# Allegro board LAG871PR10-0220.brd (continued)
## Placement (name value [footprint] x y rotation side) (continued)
PR504  0_0402_5%  [R0402_0OHM]  178.82 104.25 90 top
PR505  1M_0402_1%  [R_0402]  177.11 105.16 90 top
PR506  10K_0402_1%  [R_0402]  181.76 103.16 270 bottom
PR513  0_0402_5%  [R0402_0OHM]  127.97 25.58 180 top
PR514  1M_0402_1%  [R_0402]  126.27 25.23 270 top
PR515  21.5K_0402_1%  [R_0402]  118.05 26.87 270 top
PR516  10K_0402_1%  [R_0402]  118.94 25.1 270 top
PR601  45.3_0402_1%  [R_0402]  56.88 59.04 0 top
PR602  0_0402_5%  [R0402_0OHM]  59.97 61.64 90 top
PR603  0_0402_5%  [R0402_0OHM]  58.45 64.12 180 top
PR604  75_0402_1%  [R_0402]  56.88 59.9 0 top
PR605  100_0402_1%  [R_0402]  56.88 60.75 0 top
PR606  0_0402_5%  [R0402_0OHM]  90.57 96.79 270 top
PR608  100K_0402_5%  [R_0402]  60.1 64.12 180 top
PR610  10K_0402_1%  [R_0402]  62.46 53.79 90 top
PR611  9.31K_0402_1%  [R_0402]  60.1 65 180 top
PR612  1.91K_0402_1%  [R_0402]  59.02 58.21 0 top
PR613  97.6K_0402_1%  [R_0402]  60.73 53.75 90 top
PR614  0_0402_5%  [R0402_0OHM]  59.02 57.32 0 top
PR615  0_0402_5%  [R_0402]  72.4 54.4 90 top
PR616  0_0402_5%  [R0402_0OHM]  58.94 55.61 0 top
PR617  4.3K_0402_1%  [R_0402]  63.28 53.77 90 top
PR618  49.9_0402_1%  [R_0402]  59.02 59.04 0 top
PR619  2.2_0603_5%  [R_0603]  95.14 97.61 270 bottom
PR620  0_0402_5%  [R0402_0OHM]  58.94 54.72 0 top
PR621  316_0402_1%  [R_0402]  66.03 51.78 90 top
PR622  2.49K_0402_1%  [R_0402]  67.72 52.69 180 top
PR623  2K_0402_1%  [R_0402]  65.14 53.57 0 top
PR624  3.65K_0603_1%  [R_0603]  91.69 90.61 180 top
PR625  0_0402_5%  [R0402_0OHM]  59.04 59.9 0 top
PR626  10_0402_1%  [R_0402]  59.02 60.75 0 top
PR627  4.7_1206_5%  [R_1206]  94.11 91.99 270 top
PR628  4.99K_0402_1%  [R_0402]  82.99 86.06 180 top
PR629  86.6K_0402_1%  [R_0402]  74.19 54.41 180 top
PR630  2.49K_0402_1%  [R_0402]  70.34 65.63 90 top
PR631  27.4K_0402_1%  [R_0402]  61.62 52.85 0 top
PR632  1K_0402_1%  [R_0402]  71.98 51.63 0 top
PR633  11K_0402_1%  [R_0402]  69.66 52.61 0 top
PR634  0_0402_5%  [R_0402]  73.27 52.7 0 top
PR635  10K_0402_1%  [R_0402]  74.22 56.17 180 top
PR636  634_0402_1%  [R_0402]  62.93 65.45 90 top
PR638  523_0402_1%  [R_0402]  71.43 52.65 90 top
PR639  3.09K_0402_1%  [R_0402]  74.21 57.88 180 top
PR640  365_0402_1%  [R_0402]  74.23 65.46 0 top
PR641  1K_0402_1%  [R_0402]  62.14 67.77 90 top
PR642  2.61K_0402_1%  [R_0402]  90.63 89.47 270 top
PR643  11K_0402_1%  [R_0402]  65.22 70.56 270 top
PR644  1K_0402_1%  [R_0402]  74.35 67.2 270 top
PR645  316_0402_1%  [R_0402]  74.16 60.76 180 top
PR646  316_0402_1%  [R_0402]  67.51 65.65 90 top
PR647  27.4K_0402_1%  [R_0402]  75.04 55.26 90 top
PR648  1.91K_0402_1%  [R_0402]  74.15 59.05 180 top
PR649  1.62K_0402_1%  [R_0402]  66.55 65.74 90 top
PR650  2K_0402_1%  [R_0402]  73.23 59.9 0 top
PR651  39.2K_0402_1%  [R_0402]  71.53 66.52 0 top
PR652  2K_0402_1%  [R_0402]  68.41 65.63 90 top
PR653  20M_0402_5%  [R_0402]  76.61 62.44 90 top
PR656  11K_0402_1%  [R_0402]  74.21 63.66 90 top
PR657  4.42K_0402_1%  [R_0402]  87.43 66.8 0 top
PR658  20M_0402_5%  [R_0402]  69.29 51.68 270 top
PR659  0_0402_5%  [R0402_0OHM]  79.95 86.49 180 bottom
PR660  3.9_0603_1%  [R_0603]  76.26 85.01 90 bottom
PR661  3.65K_0603_1%  [R_0603]  82.21 69.55 270 top
PR662  0_0402_5%  [R0402_0OHM]  71.84 66.13 90 bottom
PR663  4.7_1206_5%  [R_1206]  82.72 93.5 180 top
PR664  0_0402_5%  [R0402_0OHM]  72.64 66.13 90 bottom
PR665  3.9_0603_1%  [R_0603]  71.12 70.37 0 bottom
PR666  10_0402_1%  [R_0402]  83.93 88 180 top
PR667  3.65K_0603_1%  [R_0603]  87.33 91.04 90 top
PR668  100K_0402_1%  [R_0402]  88.33 92.56 270 top
PR669  4.7_1206_5%  [R_1206]  81.03 71.11 0 top
PR670  100K_0402_1%  [R_0402]  88.42 77.27 270 top
PR671  0_0402_5%  [R0402_0OHM]  76.02 76.02 90 bottom
PR672  3.9_0603_1%  [R_0603]  74.62 79.67 0 bottom
PR673  10_0402_1%  [R_0402]  89.24 77.27 270 top
PR674  3.65K_0603_1%  [R_0603]  85.79 76.14 90 top
PR675  100K_0402_1%  [R_0402]  84.77 76.46 270 top
PR676  4.7_1206_5%  [R_1206]  83.59 77.68 90 top
PR677  100K_0402_1%  [R_0402]  83.88 74.8 0 top
PR678  100_0402_1%  [R_0402]  58.94 56.37 0 top
PR679  0_0402_5%  [R0402_0OHM]  92.47 92.83 270 top
PR680  1_0603_5%  [R_0603]  71.24 69.29 270 bottom
PR687  0_0402_5%  [R0402_0OHM]  80.99 86.56 90 bottom
PR688  1_0603_5%  [R_0603]  79.53 87.04 180 top
PR691  1_0603_5%  [R_0603]  74.89 77.13 90 bottom
PR692  0_0402_5%  [R0402_0OHM]  76.32 75.24 0 bottom
PR693  11.8K_0402_1%  [R_0402]  59.84 53.03 90 top
PR700  0.01_1206_1%  [R_1206_4P-D]  51.75 83.74 0 bottom
PR701  1_0603_1%  [R_0603]  44.11 59.48 270 bottom
PR702  1_0603_1%  [R_0603]  47.06 61.2 270 bottom
PR703  0_0603_5%  [R_0603]  40.33 56.37 0 top
PR704  3.3_0603_1%  [R_0603]  44.35 57.52 0 top
PR705  442K_0402_1%  [R_0402]  39.02 55.31 0 top
PR706  100K_0402_5%  [R_0402]  39.94 54.43 180 top
PR707  4.7_0603_5%  [R_0603]  52.08 56.67 0 top
PR708  1_0805_5%~D  [R_0805]  43.69 60.04 90 top
PR709  0_0402_5%  [R0402_0OHM]  38.66 53.46 0 top
PR710  100K_0402_1%  [R_0402]  54.48 58.63 180 top
PR711  0.005_1206_1%  [R_1206_4P-D]  225.7 40.61 0 bottom
PR712  0_0402_5%  [R_0402]  53.56 57.8 0 top
PR713  0_0402_5%  [R0402_0OHM]  40.9 53.34 0 top
PR714  4.7_0603_5%  [R_0603]  52.86 55.44 180 top
PR715  0_0402_5%  [R0402_0OHM]  40.9 52.55 0 top
PR716  154K_0402_1%  [R_0402]  55.22 58.65 270 top
PR717  4.7_1206_5%  [R_1206]  59.89 72.45 180 top
PR718  4.7_1206_5%  [R_1206]  60.44 74.44 180 top
PR719  0_0402_5%  [R0402_0OHM]  40.9 51.77 0 top
PR720  1M_0402_1%  [R_0402]  42.51 69.75 180 top
PR721  0_0402_5%  [R0402_0OHM]  51.37 53.19 0 top
PR722  0_0402_5%  [R0402_0OHM]  40.95 50.79 0 top
PR723  100K_0402_1%  [R_0402]  41.24 49.21 270 top
PR724  100K_0402_1%  [R_0402]  41.2 50.03 0 top
PR725  105K_0402_1%  [R_0402]  44.7 49.26 270 top
PR726  100K_0402_1%  [R_0402]  43.88 48.3 90 top
PR727  0_0402_5%  [R0402_0OHM]  40.21 48.26 90 top
PR728  499_0402_1%  [R_0402]  45.5 49.27 270 top
PR729  0_0402_5%  [R0402_0OHM]  48.86 49.27 270 top
PR731  0_0402_5%  [R0402_0OHM]  49.69 49.27 270 top
PR733  1_0603_1%  [R_0603]  53.3 50.26 0 top
PR734  1_0603_1%  [R_0603]  53.37 48.16 270 top
PR735  0_0402_5%  [R_0402]  46.53 64.83 180 top
PR736  0_0402_5%  [R0402_0OHM]  47.29 63.95 90 top
PR737  0_0402_5%  [R0402_0OHM]  48.08 63.95 90 top
PR738  100_0402_5%  [R_0402]  51.06 46.87 270 top
PR739  100K_0402_1%  [R_0402]  45.71 68.93 0 top
PR740  0_0402_5%  [R0402_0OHM]  43.75 64.8 180 top
PR741  0_0402_5%  [R0402_0OHM]  44.95 70.12 270 top
PR743  0_0402_5%  [R0402_0OHM]  47.21 49.27 270 top
PR744  100K_0402_1%  [R_0402]  42.08 64.78 90 top
PR745  0_0402_5%  [R_0402]  43.08 48.3 90 top
PR746  0_0402_5%  [R_0402]  36.95 53.02 0 top
PR800  422K_0402_1%  [R_0402]  49.57 75.95 180 top
PR801  300K_0402_5%  [R_0402]  43.42 89.91 180 top
PR802  300K_0402_5%  [R_0402]  50.17 77.38 270 bottom
PR803  499K_0402_1%  [R_0402]  44.02 85.03 0 bottom
PR804  499K_0402_1%  [R_0402]  48.39 77.41 270 bottom
PR805  1.8M_0402_1%  [R_0402]  48.67 76.73 0 top
PR806  1K_0402_1%  [R_0402]  42.23 73.64 90 top
PR807  100K_0402_5%  [R_0402]  42.51 90.7 0 top
PR808  100K_0402_5%  [R_0402]  47.34 93.16 0 top
PR809  102K_0402_1%  [R_0402]  43.12 73.64 90 top
PR810  100K_0402_5%  [R_0402]  45.36 103.86 270 top
PR811  49.9K_0402_1%  [R_0402]  38.15 93.01 90 top
PR812  49.9K_0402_1%  [R_0402]  34.31 95.08 90 top
PR813  100K_0402_5%  [R_0402]  44.58 103.88 180 top
PR814  0_0402_5%  [R0402_0OHM]  47.43 99.07 180 top
PR815  37.4K_0402_1%  [R_0402]  44.89 73.65 0 top
PR816  0_0402_5%  [R0402_0OHM]  37.33 93.02 90 top
PR817  24.9K_0402_1%  [R_0402]  46.86 74.61 0 top
PR818  0_0402_5%  [R0402_0OHM]  36.9 98.36 180 top
PR819  100K_0402_5%  [R_0402]  36.53 93.01 90 top
PR820  0_0402_5%  [R0402_0OHM]  44.84 94.9 180 top
PR821  100K_0402_5%  [R_0402]  42.86 101.64 270 top
PR822  100K_0402_5%  [R_0402]  40.45 103.1 0 top
PR823  100K_0402_5%  [R_0402]  42.53 87.29 90 top
PR824  100K_0402_5%  [R_0402]  36.96 105.99 270 top
PR825  100K_0402_5%  [R_0402]  34.3 105.99 270 top
PR826  0_0402_5%  [R0402_0OHM]  33.47 105.99 270 top
PR827  0_0402_5%  [R0402_0OHM]  35.29 100.26 90 top
PR828  100K_0402_5%  [R_0402]  38.61 105.07 90 top
PR829  0_0402_5%  [R0402_0OHM]  52.1 105.95 0 top
PR830  100K_0402_5%  [R_0402]  37.79 105.07 90 top
PR831  499K_0402_1%  [R_0402]  46.81 84.63 270 top
PR832  102K_0402_1%  [R_0402]  42.41 80.38 0 top
PR833  100K_0402_5%  [R_0402]  42.18 106.04 180 top
PR834  0_0402_5%  [R0402_0OHM]  36.86 100.17 90 top
PR835  47K_0402_1%  [R_0402]  41.66 84.78 270 top
PR836  0_0402_5%  [R0402_0OHM]  43.36 86.04 180 top
PR838  100K_0402_5%  [R_0402]  36.14 105.99 270 top
PR839  100K_0402_5%  [R_0402]  42.18 106.86 180 top
PR840  0_0402_5%  [R0402_0OHM]  42.45 83.86 90 top
PR841  0_0402_5%  [R_0402]  37.86 100.16 90 top
PR842  97.6K_0402_1%  [R_0402]  48.55 80.26 0 top
PR843  37.4K_0402_1%  [R_0402]  43.33 78.61 180 top
PR844  0_0402_5%  [R0402_0OHM]  41.27 105.21 0 top
PR845  0_0402_5%  [R_0402]  41.27 104.39 0 top
PR846  10K_0402_5%  [R_0402]  42.68 95.19 270 top
PR851  100K_0402_5%  [R_0402]  43.65 103.05 0 top
PR852  100K_0402_5%  [R_0402]  42.85 102.43 90 top
PR853  0_0402_5%  [R0402_0OHM]  44.23 94.13 0 top
PR854  0_0402_5%  [R0402_0OHM]  47.57 92.41 270 top
PR855  10K_0402_5%  [R_0402]  43.45 93.61 270 top
PR856  0_0402_5%  [R_0402]  43.54 96.63 270 top
PR857  0_0402_5%  [R0402_0OHM]  44.32 95.71 90 top
PR858  0_0402_5%  [R0402_0OHM]  41.64 95.66 90 top
PR859  0_0402_5%  [R0402_0OHM]  47.07 90.67 180 top
PR860  0_0402_5%  [R_0402]  45.79 88.88 90 top
PR861  0_0402_5%  [R0402_0OHM]  38.23 97.33 90 top
PR862  100K_0402_5%  [R_0402]  45.84 75.18 0 bottom
PR865  100K_0402_5%  [R_0402]  50.87 96.54 180 top
PR866  0_0402_5%  [R0402_0OHM]  42.41 81.16 0 top
PR870  499K_0402_1%  [R_0402]  49.46 79.47 180 top
PR892  22_0805_5%  [R_0805]  60.98 91.24 270 bottom
PR893  22_0805_5%  [R_0805]  59.02 94.28 180 bottom
PR953  100_0402_5%  [R_0402]  41.28 40.81 90 bottom
PR954  100_0402_5%  [R_0402]  40.52 40.81 90 bottom
PR955  100_0402_5%  [R_0402]  37.6 40.24 90 bottom
PR956  0_0402_5%  [R_0402]  36.77 40.24 90 bottom
PR3001  0_0402_5%  [R_0402]  48.53 51.86 180 bottom
PR3002  200K_0402_1%  [R_0402]  53.04 61.93 270 bottom
PR3003  300K_0402_1%  [R_0402]  53.82 61.92 270 bottom
PR3004  200K_0402_1%  [R_0402]  47.81 58.81 0 bottom
PR3005  100K_0402_1%  [R_0402]  49.98 57.4 180 bottom
PR3006  0_0402_5%  [R_0402]  45.55 66.22 180 bottom
PR3007  237K_0402_1%  [R_0402]  44.63 65.46 0 bottom
PR3008  43.2K_0402_1%  [R_0402]  46.41 64.19 0 bottom
PR3009  14.7K_0402_1%  [R_0402]  48.95 60.43 180 bottom
PR3010  147K_0402_1%  [R_0402]  48.95 61.22 180 bottom
PR3011  43.2K_0402_1%  [R_0402]  47.33 62.41 180 bottom
PR3012  1K_0201_1%  [R_0201]  52.34 61.47 270 bottom
PR3013  1K_0201_1%  [R_0201]  51.66 63.28 180 bottom
PU2  RT9058-33GX_SOT89-3  [AP2204R-5P0TRG1_SOT89-3]  63.34 93.36 0 bottom
PU3  MC74VHC1G08DFT2G_SC70-5  [TC7SH08FU_SSOP5]  51.63 93.91 270 top
PU100  -  [SY8288BRAC_QFN20_3X3]  191.58 98.97 270 top
PU102  SYV828CRAC_QFN20_3X3  [SY8288CRAC_QFN20_3X3]  43.54 26.66 90 top
PU200  -  [SY8210AQVC_QFN19_4X3]  223.44 27.3 180 top
PU301  SY8286RAC_QFN20_3X3  [SY8288RAC_QFN20_3X3]  190.78 108.94 0 top
PU401  SY8057BQDC_QFN16_3X3  [SY8057QDC_QFN16_3X3]  83.31 28.18 0 top
PU402  SY8057CQDC_QFN16_3X3  [SY8057QDC_QFN16_3X3]  185.21 26.78 180 top
PU501  -  [RT8097ALGE_SOT23-6]  178.8 104.62 90 bottom
PU503  EM1109V-AD_DFN3308-8_3X3  [AP7361C-FGE-7_U-DFN3030-8_3X3]  120.85 26.55 270 top
PU602  ISL95857CHRTZ-T_TQFN40_5X5  [ISL62883CHRTZ-T_TQFN40_5X5-S]  64.52 56.53 0 top
PU610  FDMF3035_PQFN31_5X5  [NCP302045MNTWG_PQFN33_5X5]  79.14 87.66 180 bottom
PU612  FDMF3035_PQFN31_5X5  [NCP302045MNTWG_PQFN33_5X5]  73.82 68.11 90 bottom
PU613  FDMF3035_PQFN31_5X5  [NCP302045MNTWG_PQFN33_5X5]  77.29 77.37 90 bottom
PU614  ISL95808HRZ-TS2778_DFN8_2X2~D  [ISL95808HRZ-TS2378_DFN8_2X2-S]  92.97 96.34 180 top
PU700  ISL9538BHRTZ-T_TQFN32_4X4  [ISL88738HRTZ-T_TQFN32_4X4]  48.98 52.45 180 top
PU701  MC74VHC1G08DFT2G_SC70-5  [TC7SH08FU_SSOP5]  44.89 67.81 180 top
PU800  AS393MMTR-G1_MSOP8  [LM393DGKR_VSSOP8]  45.2 76.24 90 top
PU801  MC74VHC1G08DFT2G_SC70-5  [TC7SH08FU_SSOP5]  46.4 91.87 90 top
PU3000  -  [AZV3002RL-7_U-FLGA8_1P65X1P65]  51.28 61.11 180 bottom
QC2  PJX138K_SOT563-6  [DMN63D8LV-7_SOT563-6]  172.85 77.46 270 bottom
QC4  PJX138K_SOT563-6  [DMN63D8LV-7_SOT563-6]  169.46 96.9 180 bottom
QC6  -  [L2N7002WT1G_SC-70-3]  174.97 60.24 180 top
QC7  NTK3139PT1G_SOT723-3  [PW567EA_SOT-723-3]  172.03 62.05 180 top
QE2  PJX138K_SOT563-6  [DMN63D8LV-7_SOT563-6]  279.6 64.96 0 top
QE3  -  [LMBT3904WT1G_SC70-3]  121.33 75.33 0 top
QE4  -  [LMBT3904WT1G_SC70-3]  176.41 97.78 270 bottom
QE5  -  [LMBT3904WT1G_SC70-3]  17.16 27.37 270 bottom
QE6  -  [LMBT3904WT1G_SC70-3]  89.29 96.44 180 bottom
QE7  -  [LMBT3904WT1G_SC70-3]  208.16 37.65 180 bottom
QE11  -  [L2N7002WT1G_SC-70-3]  171.4 100.45 270 bottom
QE12  -  [L2N7002WT1G_SC-70-3]  263.52 86.35 180 top
QE15  LP2301BLT1G_SOT23-3  [LP2301ALT1G_SOT23-3]  270.26 68.79 180 top
QE17  -  [L2N7002WT1G_SC-70-3]  274.91 66.56 90 top
QR1  -  [L2N7002WT1G_SC-70-3]  286.58 50.16 180 top
QV1  -  [AO6405_TSOP6]  91.47 99.2 0 bottom
QV2  -  [2N7002KTB_SOT523-3]  99.71 101.78 180 bottom
QV3  L2N7002DW1T1G_SC88-6  [DMN65D8LDW-7_SOT363-6]  9.33 54.98 0 bottom
QV4  -  [2N7002KTB_SOT523-3]  15.69 61.33 90 top
QV5  -  [2N7002KTB_SOT523-3]  16.17 67.43 0 top
QV7  -  [2N7002KTB_SOT523-3]  80.7 106.79 90 top
QV8  NTK3139PT1G_SOT723-3  [PW567EA_SOT-723-3]  78.21 108.72 0 top
QV18  -  [MMBT3906H_SOT23-3]  75.02 104.15 180 top
QV19  -  [LMBT3904WT1G_SC70-3]  88.14 100.45 90 top
QV20  -  [MMBT3906H_SOT23-3]  93.41 106 180 top
QV21  -  [LMBT3904WT1G_SC70-3]  89.48 100.45 270 top
QZ1  NTK3139PT1G_SOT723-3  [PW567EA_SOT-723-3]  52.25 107.98 0 top
QZ3  -  [LMUN5111T1G_SC70-3]  306.09 9.14 0 bottom
QZ7  L2N7002DW1T1G_SC88-6  [DMN65D8LDW-7_SOT363-6]  308.52 69.64 180 bottom
QZ15  -  [PJE138K_SOT523-3]  248.56 37.58 0 bottom
QZ17  -  [PJE138K_SOT523-3]  269.02 54.37 0 top
QZ18  NTK3139PT1G_SOT723-3  [PW567EA_SOT-723-3]  308.18 94.23 270 bottom
QZ21  -  [LMBT3904WT1G_SC70-3]  298.99 12.44 180 top
QZ22  -  [PJE138K_SOT523-3]  30.79 32.25 0 top
RA3  0_0603_5%  [R0603_0OHM]  282.96 34.79 270 top
RA5  2.2K_0402_5%  [R_0402]  288.01 39.73 180 top
RA6  2.2K_0402_5%  [R_0402]  288.01 40.62 180 top
RA7  16.2_0402_1%  [R_0402]  287.85 37.83 90 top
RA8  16.2_0402_1%  [R_0402]  288.93 36.71 270 top
RA9  33_0402_5%  [R_0402]  274.57 35.36 0 top
RA12  1K_0402_5%  [R_0402]  282.96 56.31 90 top
RA13  1K_0402_5%  [R_0402]  287.71 56.95 0 top
RA14  22_0402_5%  [R_0402]  276.75 39.68 180 top
RA17  33_0402_5%  [R_0402]  276.73 37.26 180 top
RA18  10K_0402_5%  [R_0402]  273.96 44.57 180 top
RA35  0_0402_5%  [R0402_0OHM]  295.86 43.8 135 top
RA36  0_0402_5%  [R0402_0OHM]  283.34 49.57 90 top
RA37  0_0402_5%  [R0402_0OHM]  295.92 33.28 270 top
RA44  100K_0402_5%  [R_0402]  286.71 47.8 90 top
RA45  10K_0402_5%  [R_0402]  286.14 58.08 90 top
RA48  0_0201_5%  [R0201_0OHM]  273.37 46.64 270 top
RA50  0_0201_5%  [R_0201]  272.36 44.41 90 top
RA51  10K_0402_5%  [R_0402]  284.74 56.31 90 top
RA52  100K_0402_5%  [R_0402]  275.84 41.14 0 top
RA53  0_0402_5%  [R0402_0OHM]  286.33 42.08 0 top
RA54  0_0402_5%  [R_0402]  285.76 42.84 0 top
RA59  100K_0402_1%  [R_0402]  275.98 46.4 270 top
RA60  200K_0402_1%  [R_0402]  275.23 45.97 180 top
RA61  100K_0402_1%  [R_0402]  277.57 44.88 135 top
RA66  10K_0402_5%  [R_0402]  304.88 17.56 270 bottom
RA67  10K_0402_5%  [R_0402]  305.7 17.56 270 bottom
RC2  100K_0402_5%  [R_0402]  168.08 88.51 0 bottom
RC5  121_0402_1%  [R_0402]  140.12 74.83 90 top
RC7  100_0402_1%  [R_0402]  140.11 73.84 270 top
RC8  24.9_0402_1%  [R_0402]  130.05 96.15 270 top
RC10  200_0402_1%  [R_0402]  160.27 83.24 0 top
RC11  1K_0402_1%  [R_0402]  169.32 70.91 180 bottom
RC12  1K_0402_5%  [R_0402]  171.73 78.71 180 bottom
RC14  1K_0402_5%  [R_0402]  172.59 78.71 0 bottom
RC15  1K_0402_5%  [R_0402]  162.74 82.92 0 bottom
RC19  33_0402_5%  [R_0402]  159.48 60.35 270 top
RC24  0_0201_5%  [R_0201]  185.81 73.06 270 bottom
RC25  4.99_0201_1%  [R_0201]  184.37 74.1 0 bottom
RC26  4.99_0201_1%  [R_0201]  185.93 75.22 270 bottom
RC27  4.99_0201_1%  [R_0201]  181.07 74.23 0 bottom
RC28  0_0201_5%  [R0201_0OHM]  179.93 75.05 0 bottom
RC29  4.99_0201_1%  [R_0201]  178.66 74.16 0 bottom
RC30  4.99_0201_1%  [R_0201]  177.39 74.16 0 bottom
RC31  0_0201_5%  [R_0201]  175.84 74.2 270 bottom
RC32  0_0201_5%  [R0201_0OHM]  181.32 75.69 0 top
RC33  49.9_0201_1%  [R_0201]  179.93 75.05 0 top
RC35  33_0201_1%  [R_0201]  179.29 76.07 0 bottom
RC46  2.2K_0402_5%  [R_0402]  166.59 59.47 90 top
RC47  113_0402_1%  [R_0402]  152.16 97.94 90 top
RC48  1K_0402_5%  [R_0402]  155.33 55.57 270 top
RC49  1K_0402_5%  [R_0402]  150.55 96.2 0 top
RC50  100_0402_1%  [R_0402]  150.04 95.24 0 top
RC51  10K_0402_5%  [R_0402]  179.8 65.16 270 top
RC53  10K_0402_5%  [R_0402]  169.27 60.39 270 top
RC56  20K_0402_5%  [R_0402]  150.46 53.92 270 top
RC57  20K_0402_5%  [R_0402]  152.24 53.85 270 top
RC59  200K_0402_1%  [R_0402]  155.26 95.42 90 bottom
RC60  0_0201_5%  [R_0201]  198.21 74.49 270 top
RC61  100K_0402_5%  [R_0402]  169.31 67.88 180 bottom
RC62  100K_0402_5%  [R_0402]  171.67 69.96 180 bottom
RC63  10K_0402_5%  [R_0402]  173.92 86.86 0 top
RC65  100K_0402_5%  [R_0402]  194.85 72.05 90 top
RC66  10M_0402_5%  [R_0402]  150.54 59.44 270 top
RC67  1K_0402_5%  [R_0402]  157.8 59.48 90 top
RC68  10K_0402_5%  [R_0402]  159.55 56.52 270 top
RC69  1M_0402_5%  [R_0402]  149.64 53.92 270 top
RC71  1K_0402_5%  [R_0402]  135.76 99.49 90 bottom
RC72  10K_0402_5%  [R_0402]  149.03 64.32 0 top
RC73  10K_0402_5%  [R_0402]  151.06 62.8 0 top
RC75  10K_0402_5%  [R_0402]  145.12 64.57 270 top
RC77  1K_0402_5%  [R_0402]  130.24 97.23 270 bottom
RC78  62_0402_5%  [R_0402]  138.5 99.51 270 bottom
RC82  10K_0201_5%  [R_0201]  170.48 95.94 180 bottom
RC84  499_0402_1%  [R_0402]  115.79 103.51 270 bottom
RC86  51_0201_5%  [R_0201]  103.26 95.14 90 top
RC87  1K_0201_5%  [R_0201]  104.15 96.48 90 top
RC92  33_0402_5%  [R_0402]  148.62 52.94 90 top
RC93  33_0402_5%  [R_0402]  147.79 52.94 90 top
RC94  100K_0402_5%  [R_0402]  171.67 68.57 180 bottom
RC95  100K_0402_5%  [R_0402]  182.06 57.7 90 top
RC96  100K_0402_5%  [R_0402]  170.75 71.61 0 bottom
RC101  20K_0402_5%  [R_0402]  164.86 75.69 180 bottom
RC104  10K_0201_5%  [R_0201]  170.86 97.13 90 bottom
RC106  49.9_0201_1%  [R_0201]  142.31 74.95 90 top
RC107  49.9_0201_1%  [R_0201]  145.76 75.32 0 top
RC108  49.9_0201_1%  [R_0201]  112.46 95.21 90 top
RC109  49.9_0201_1%  [R_0201]  115.07 95.14 90 top
RC116  200_0402_1%  [R_0402]  158.89 64.5 0 top
RC120  1K_0201_1%  [R_0201]  115.58 99.07 270 top
RC121  0_0201_5%  [R0201_0OHM]  69.73 96.62 270 top
RC122  0_0201_5%  [R_0201]  69.01 96.58 180 top
RC123  1K_0201_5%  [R_0201]  63.41 98.02 180 top
RC124  1K_0201_5%  [R_0201]  63.41 97.26 180 top
RC125  1.5K_0201_5%  [R_0201]  103.83 101.37 90 top
RC126  1K_0201_5%  [R_0201]  59.21 95.21 270 top
RC128  0_0201_5%  [R0201_0OHM]  56.41 99.14 270 top
RC129  0_0201_5%  [R_0201]  57.04 99.14 270 top
RC130  51_0201_5%  [R_0201]  106.64 94.52 90 bottom
RC131  51_0201_5%  [R_0201]  105.48 96.48 90 top
RC132  150_0402_5%  [R_0402]  60.15 94.82 270 top
RC133  1.5K_0201_5%  [R_0201]  55.73 99.09 90 top
RC134  51_0201_5%  [R_0201]  101.42 95.21 90 top
RC135  100_0201_5%  [R_0201]  106.05 96.48 90 top
RC136  51_0201_5%  [R_0201]  107.13 96.73 90 bottom
RC137  3K_0402_5%  [R_0402]  60.67 99.41 90 top
RC138  51_0201_5%  [R_0201]  85.68 107.4 90 top
RC139  51_0201_5%  [R_0201]  57.16 96.41 180 top
RC150  100_0402_1%  [R_0402]  124.96 99.41 0 bottom
RC151  100_0402_1%  [R_0402]  125.88 98.59 180 bottom
RC153  0_0603_5%  [R0603_0OHM]  137.55 97.64 270 bottom
RC154  56_0402_1%  [R_0402]  116.87 106 270 bottom
RC155  220_0402_5%  [R_0402]  117.44 102.59 90 bottom
RC156  100_0402_1%  [R_0402]  116.04 106 270 bottom
RC157  0_0201_5%  [R0201_0OHM]  116.62 102.59 90 bottom
RC158  43_0402_5%  [R_0402]  117.89 106 270 bottom
RC159  0_0201_5%  [R0201_0OHM]  118.46 102.59 90 bottom
RC160  100_0402_1%  [R_0402]  108.93 97.6 270 bottom
RC161  100_0402_1%  [R_0402]  108.08 96.69 90 bottom
RC163  100_0402_1%  [R_0402]  96.09 78.6 0 top
RC164  100_0402_1%  [R_0402]  135.16 95.97 180 top
RC165  0_0201_5%  [R0201_0OHM]  96.88 77.84 180 top
RC166  100_0402_1%  [R_0402]  134.36 98.29 0 top
RC173  0.01_0603_1%  [R_0603-NPM]  149.03 95.74 180 top
RC175  0.01_0603_1%  [R_0603]  166.64 95.9 270 bottom
RC176  2.2K_0402_5%  [R_0402]  153.55 100.31 90 top
RC178  2.2K_0402_5%  [R_0402]  171.95 86.86 0 top
RC183  2.2K_0402_5%  [R_0402]  181.7 61.6 270 top
RC187  4.7K_0402_5%  [R_0402]  146.91 52.94 90 top
RC189  10K_0402_5%  [R_0402]  178.97 65.16 270 top
RC190  10K_0402_5%  [R_0402]  178.15 65.16 270 top
RC214  0_0201_5%  [R_0201]  168.36 63.66 90 top
RC215  0_0201_5%  [R0201_0OHM]  167.67 55.6 90 top
RC216  0_0402_5%  [R0402_0OHM]  63.14 99.55 180 top
RC217  0_0201_5%  [R_0201]  59.21 93.43 90 top
RC218  1K_0201_1%  [R_0201]  136.54 101.1 270 top
RC219  49.9_0201_1%  [R_0201]  118.75 106.05 270 bottom
RC220  100K_0402_1%  [R_0402]  166.84 56.52 270 top
RC221  0_0201_5%  [R0201_0OHM]  301.68 26.46 90 bottom
RC222  1K_0402_5%  [R_0402]  301.76 28.28 180 bottom
RC229  100K_0402_5%  [R_0402]  170.4 56.48 270 top
RC230  100K_0402_5%  [R_0402]  168.62 56.48 270 top
RC231  100K_0402_5%  [R_0402]  145.97 54.92 180 top
RC232  100K_0402_5%  [R_0402]  161.38 56.52 270 top
RC233  100K_0402_5%  [R_0402]  163.16 56.52 270 top
RC234  100K_0402_5%  [R_0402]  164.94 56.52 270 top
RC235  150_0402_5%  [R_0402]  60.16 93.1 270 top
RC236  10K_0201_5%  [R_0201]  61.07 92.74 270 top
RC237  100K_0402_5%  [R_0402]  195.69 74.99 180 top
RC239  0_0201_5%  [R0201_0OHM]  65.92 98.46 270 top
RC240  0_0201_5%  [R0201_0OHM]  66.68 98.46 270 top
RC241  1.5K_0201_5%  [R_0201]  62.34 94.48 0 top
RC243  0_0201_5%  [R0201_0OHM]  174.39 87.69 0 top
RC244  10K_0402_1%  [R_0402]  160.58 57.97 0 top
RC248  2.2K_0402_5%  [R_0402]  174.39 88.51 0 top
RC266  4.7K_0402_5%  [R_0402]  162.24 79.66 0 bottom
RC277  4.7K_0402_5%  [R_0402]  167.28 81.08 0 top
RC278  10K_0402_5%  [R_0402]  180.9 61.6 270 top
RC279  10K_0402_5%  [R_0402]  180.09 61.6 270 top
RC288  10K_0402_5%  [R_0402]  168.4 71.72 0 top
RC289  33_0402_5%  [R_0402]  194.03 73.07 180 bottom
RC292  10K_0402_5%  [R_0402]  179.26 61.6 270 top
RC297  0_0201_5%  [R0201_0OHM]  178.97 67.67 270 top
RC298  0_0201_5%  [R_0201]  131.13 95.21 90 bottom
RC299  33_0402_5%  [R_0402]  188.79 63.23 90 top
RC302  0_0201_5%  [R_0201]  181.32 75.69 0 bottom
RC317  150K_0402_5%  [R_0402]  151.06 63.62 0 top
RC318  2.2K_0402_5%  [R_0402]  170.74 75.14 0 bottom
RC319  2.2K_0402_5%  [R_0402]  174.04 77.16 270 bottom
RC323  10K_0402_5%  [R_0402]  158.63 59.48 90 top
RC328  0_0201_5%  [R0201_0OHM]  104.91 96.48 90 top
RC337  0_0201_5%  [R0201_0OHM]  152.53 95.59 90 top
RC344  10K_0402_5%  [R_0402]  158.73 56.52 270 top
RC345  100K_0402_5%  [R_0402]  170 77.16 270 bottom
RC347  499_0402_1%  [R_0402]  169.11 84.31 90 bottom
RC348  499_0402_1%  [R_0402]  169.93 83.42 90 bottom
RC362  1K_0402_5%  [R_0402]  168.4 72 0 bottom
RC363  1K_0402_5%  [R_0402]  168.4 72.89 0 bottom
RC366  15_0402_5%  [R_0402]  164.49 60.35 270 top
RC367  15_0402_5%  [R_0402]  163.67 60.35 270 top
RC368  15_0402_5%  [R_0402]  162.84 60.35 270 top
RC369  15_0402_5%  [R_0402]  162.02 60.35 270 top
RC397  20K_0402_5%  [R_0402]  167.28 81.91 0 top
RC400  10K_0402_5%  [R_0402]  162.24 77.97 0 bottom
RC401  10K_0402_5%  [R_0402]  162.24 78.8 0 bottom
RC402  60.4_0402_1%  [R_0402]  153.3 96.18 90 bottom
RC405  1K_0201_1%  [R_0201]  114.5 97.76 270 top
RC406  1K_0201_1%  [R_0201]  115.16 97.78 0 top
RC407  1K_0201_1%  [R_0201]  117.04 97.3 90 top
RC409  1K_0201_1%  [R_0201]  111.83 99.79 270 bottom
RC410  1K_0201_1%  [R_0201]  108.55 99.82 0 bottom
RC411  1K_0201_1%  [R_0201]  108.55 101.09 0 bottom
RC412  1K_0201_1%  [R_0201]  115.16 97.15 0 top
RC413  1K_0201_1%  [R_0201]  112.4 99.79 270 bottom
RC414  1K_0201_1%  [R_0201]  117.04 96.62 270 top
RC415  1K_0201_1%  [R_0201]  113.04 99.79 270 bottom
RC416  1K_0201_1%  [R_0201]  111.13 95.16 270 bottom
RC417  1K_0201_1%  [R_0201]  113.07 96.58 180 bottom
RC418  1K_0201_1%  [R_0201]  108.55 99.12 0 bottom
RC419  1K_0201_1%  [R_0201]  113.1 95.14 90 bottom
RC420  0_0201_5%  [R_0201]  88.96 64.26 0 top
RC422  0.01_0603_1%  [R_0603]  146.65 102.41 180 top
RC425  0_0201_5%  [R0201_0OHM]  134.36 96.77 0 top
RC426  0_0201_5%  [R0201_0OHM]  134.36 97.47 0 top
RC429  0_0201_5%  [R0201_0OHM]  128.23 98.59 180 bottom
RC430  0_0201_5%  [R0201_0OHM]  128.23 99.41 180 bottom
RC431  100K_0402_5%  [R_0402]  175.11 64.19 180 top
RC432  499K_0402_1%  [R_0402]  173.32 64.2 270 top
RC433  49.9K_0402_1%  [R_0402]  173.32 62.49 270 top
RC435  0_0603_5%  [R_0603]  105.55 112.31 270 top
RC436  100_0201_1%  [R_0201]  89.19 66.8 0 top
RC439  0_0402_5%  [R_0402]  168.36 62.54 270 top
RC440  0_0402_5%  [R0402_0OHM]  167.54 63.67 90 top
RC441  0_0201_5%  [R_0201]  171.23 56.48 270 top
RC442  0_0201_5%  [R0201_0OHM]  172.05 56.48 270 top
RC443  4.7K_0402_5%  [R_0402]  169.37 74.1 180 bottom
RC444  20K_0402_5%  [R_0402]  168.46 74.99 0 bottom
RC445  0_0201_5%  [R0201_0OHM]  174.53 57.27 0 top
RC446  20K_0402_5%  [R_0402]  162.24 76.26 0 bottom
RC448  150_0402_1%  [R_0402]  169.31 70.92 180 top
RC451  20K_0402_5%  [R_0402]  153.76 51.37 270 top
RC452  4.7K_0402_5%  [R_0402]  153 50.45 90 top
RC454  20K_0402_5%  [R_0402]  182.25 55.04 90 top
RC502  2.2K_0402_5%  [R_0402]  154.31 100.31 90 top
RC503  2.2K_0402_5%  [R_0402]  171.95 87.62 0 top
RC504  80.6_0402_1%  [R_0402]  140.88 75.09 90 top
RC505  1K_0402_1%  [R_0402]  171.67 67.74 180 bottom
RC507  1K_0402_5%  [R_0402]  162.74 83.69 0 bottom
RC512  2.2K_0201_5%  [R_0201]  168.29 67.04 0 top
RC513  2.2K_0201_5%  [R_0201]  168.29 66.15 0 top
RC515  4.7K_0402_5%  [R_0402]  170.75 70.79 0 bottom
RC518  4.7K_0402_5%  [R_0402]  170.75 66.91 0 bottom
RC519  4.7K_0402_5%  [R_0402]  168.4 70.09 0 bottom
RC520  1K_0402_5%  [R_0402]  168.08 87.5 0 bottom
RC521  1K_0402_5%  [R_0402]  165.31 85.59 180 bottom
RC522  10K_0402_5%  [R_0402]  181.45 65.16 270 top
RC523  10K_0402_5%  [R_0402]  180.62 65.16 270 top
RC525  10K_0402_5%  [R_0402]  177.32 65.16 270 top
RC526  0_0201_5%  [R0201_0OHM]  181.32 67.67 270 top
RC528  0_0201_5%  [R0201_0OHM]  179.8 67.67 270 top
RC529  0_0201_5%  [R0201_0OHM]  178.15 67.67 270 top
RC530  0_0201_5%  [R_0201]  131.77 95.21 90 bottom
RC532  0_0402_5%  [R0402_0OHM]  151.35 59.43 0 top
RC536  10K_0402_5%  [R_0402]  152.24 51.37 270 top
RC537  4.7K_0402_5%  [R_0402]  163.95 76.57 0 bottom
RC548  0_0201_5%  [R0201_0OHM]  107.33 109.7 90 top
RC549  0_0201_5%  [R0201_0OHM]  107.91 109.7 90 top
RC555  10K_0402_5%  [R_0402]  169.31 66.4 180 bottom
RC557  10K_0402_5%  [R_0402]  174.01 85.66 180 bottom
RC558  1K_0201_1%  [R_0201]  115.22 106.05 270 bottom
RC559  0_0201_5%  [R0201_0OHM]  137.14 99.87 180 top
RC560  33_0402_5%  [R_0402]  144.11 51.16 90 top
RC561  33_0402_5%  [R_0402]  146.02 51.16 90 top
RC562  1K_0402_5%  [R_0402]  147.71 51.23 90 top
RC563  0_0201_5%  [R_0201]  90.98 66.1 180 top
RC564  0_0201_5%  [R_0201]  90.98 66.8 180 top
RC565  0_0201_5%  [R_0201]  110.14 94.59 90 bottom
RC566  0_0201_5%  [R0201_0OHM]  169.16 95.94 180 bottom
RC567  10K_0201_5%  [R_0201]  181.24 57.7 90 top
RC568  100_0201_5%  [R_0201]  101.82 97.97 0 top
RC569  51_0201_5%  [R_0201]  102.6 95.82 180 top
RC570  49.9_0201_1%  [R_0201]  188.28 72.87 270 top
RC571  49.9_0201_1%  [R_0201]  183.95 73.73 315 top
RC572  49.9_0201_1%  [R_0201]  179.67 73.97 0 top
RC573  33_0201_1%  [R_0201]  188.05 74.86 0 bottom
RC574  33_0201_1%  [R_0201]  187.65 72.93 270 bottom
RC575  33_0201_1%  [R_0201]  183.93 76 0 bottom
RC576  33_0201_1%  [R_0201]  178.78 76.83 0 bottom
RC624  49.9_0201_1%  [R_0201]  119.42 96.83 90 top
RC631  0_0201_5%  [R0201_0OHM]  108.21 94.44 90 bottom
RC632  0_0201_5%  [R0201_0OHM]  108.85 94.44 90 bottom
RC640  75K_0402_5%  [R_0402]  176.47 67.63 270 top
RC660  0_0201_5%  [R0201_0OHM]  178.7 84.04 270 bottom
RC710  33_0402_5%  [R_0402]  175.19 82.68 270 top
RC711  33_0402_5%  [R_0402]  176.54 78.4 90 top
RC723  1K_0201_1%  [R_0201]  108.55 100.45 0 bottom
RC724  20K_0402_5%  [R_0402]  176.54 80.12 90 top
RC725  10K_0402_5%  [R_0402]  165.7 60.35 270 top
RC727  0_0201_5%  [R0201_0OHM]  177.32 67.67 270 top
RC728  0_0402_5%  [R_0402]  154.44 95.42 90 bottom
RC729  0_0402_5%  [R_0402]  154.4 94.62 0 bottom
RC730  1K_0402_5%  [R_0402]  165.06 84.58 180 bottom
RC733  20K_0402_5%  [R_0402]  174.36 81.77 90 top
RC734  49.9_0201_1%  [R_0201]  188.69 74.86 0 top
RC735  0_0201_5%  [R0201_0OHM]  56.92 101.19 90 top
RC736  0_0201_5%  [R0201_0OHM]  58.1 101.19 90 top
RC737  0_0201_5%  [R0201_0OHM]  59.91 101.25 90 top
RC738  0_0201_5%  [R0201_0OHM]  198.21 71.86 90 top
RC743  10K_0402_5%  [R_0402]  173.88 86.04 180 top
RC744  10K_0402_5%  [R_0402]  167.28 83.43 180 bottom
RC745  10K_0402_5%  [R_0402]  167.47 81.91 180 bottom
RC747  100K_0402_5%  [R_0402]  170.1 60.39 270 top
RC748  10K_0402_5%  [R_0402]  171.82 82.04 0 bottom
RC749  100K_0402_5%  [R_0402]  171.82 81.21 0 bottom
RC751  10K_0402_5%  [R_0402]  154.32 96.2 180 top
RC752  71.5K_0402_1%  [R_0402]  176.47 64.24 90 top
RC753  10K_0402_5%  [R_0402]  171.82 83.5 0 bottom
RC754  10K_0402_5%  [R_0402]  174.81 85.66 0 bottom
RC757  20K_0402_5%  [R_0402]  172.93 90.23 180 top
RC758  20K_0402_5%  [R_0402]  172.93 93.59 180 top
RC759  20K_0402_5%  [R_0402]  172.93 92.77 180 top
RC760  20K_0402_5%  [R_0402]  172.93 91.05 180 top
RC761  100K_0402_5%  [R_0402]  158.77 57.27 180 top
RC763  100K_0402_5%  [R_0402]  139.79 60.64 270 top
RC764  10K_0402_5%  [R_0402]  166.77 84.58 180 bottom
RC765  10K_0402_5%  [R_0402]  168.99 86.61 180 bottom
RC766  10K_0402_5%  [R_0402]  166.96 85.59 180 bottom
RC829  1K_0402_5%  [R_0402]  167.95 77.53 0 bottom
RC830  1K_0402_5%  [R_0402]  166.95 76.56 90 bottom
RC831  4.7K_0402_5%  [R_0402]  176.79 60.69 90 top
RC832  4.7K_0402_5%  [R_0402]  175.19 83.48 90 top
RC833  100K_0402_5%  [R_0402]  177.62 60.69 90 top
RC834  100K_0402_5%  [R_0402]  151.06 61.97 0 top
RC836  10K_0402_5%  [R_0402]  175.28 90.23 180 top
RC837  10K_0402_5%  [R_0402]  175.28 93.59 180 top
RC838  10K_0402_5%  [R_0402]  175.28 91.05 180 top
RC839  10K_0402_5%  [R_0402]  175.28 92.77 180 top
RC841  10K_0402_5%  [R_0402]  178.44 61.6 270 top
RC842  20K_0402_5%  [R_0402]  174.36 83.48 90 top
RC843  10K_0201_5%  [R_0201]  167.54 94.16 0 bottom
RC844  10K_0201_5%  [R_0201]  167.54 93.53 0 bottom
RC845  0_0201_5%  [R0201_0OHM]  168.79 79.92 270 top
RC847  100K_0402_5%  [R_0402]  162.24 77.15 0 bottom
RC848  0_0201_5%  [R0201_0OHM]  141.31 61.77 90 top
RC849  8.2K_0402_5%  [R_0402]  172.17 59.47 90 top
RC850  0_0201_5%  [R0201_0OHM]  60.52 101.82 270 top
RC851  0_0201_5%  [R0201_0OHM]  57.51 101.76 270 top
RC852  0_0201_5%  [R0201_0OHM]  56.27 101.76 270 top
RC853  0_0201_5%  [R0201_0OHM]  55.07 99.69 270 top
RC854  10K_0402_5%  [R_0402]  174.59 83.42 270 bottom
RC864  0_0603_5%  [R_0603-NPM]  146.59 106.39 0 top
RC866  10K_0201_5%  [R_0201]  148.37 78.95 270 top
RC867  0_0201_5%  [R_0201]  175.33 83.48 270 bottom
RC868  75K_0402_5%  [R_0402]  187.65 59 270 top
RD4  0_0201_5%  [R_0201]  123.96 36.93 270 top
RD5  0_0201_5%  [R0201_0OHM]  123.39 36.34 90 top
RD6  0_0201_5%  [R_0201]  125.99 37.24 270 top
RD7  0_0201_5%  [R0201_0OHM]  125.36 36.66 90 top
RD8  0_0201_5%  [R_0201]  103.19 30.19 90 top
RD9  0_0201_5%  [R0201_0OHM]  103.19 31.4 90 top
RD10  0_0603_5%  [R0603_0OHM]  122.87 43.03 180 top
RD11  470_0402_1%  [R_0402]  144.82 31.48 180 top
RD12  0_0201_5%  [R0201_0OHM]  143.01 30.54 0 top
RD14  1K_0402_5%  [R_0402]  94.39 26.74 180 top
RD15  1K_0402_1%  [R_0402]  99.94 27.31 90 top
RD16  1K_0402_1%  [R_0402]  100.75 28.22 270 top
RD17  2_0402_1%  [R_0402]  101.56 28.22 270 top
RD18  24.9_0402_1%  [R_0402]  103.28 28.19 270 top
RD19  100K_0402_5%  [R_0402]  91.22 66.36 180 bottom
RD20  0_0201_5%  [R_0201]  199.61 33.9 0 top
RD21  0_0201_5%  [R0201_0OHM]  200.2 33.32 180 top
RD22  0_0201_5%  [R0201_0OHM]  201.66 33.9 180 top
RD23  0_0201_5%  [R_0201]  201.07 33.32 0 top
RD24  0_0201_5%  [R_0201]  183.42 35.29 270 top
RD25  0_0201_5%  [R0201_0OHM]  183.42 33.5 90 top
RD26  0_0603_5%  [R0603_0OHM]  199.86 36.68 90 top
RD27  1K_0402_5%  [R_0402]  94.69 27.74 135 top
RD28  1K_0402_1%  [R_0402]  172.21 28.38 0 top
RD29  1K_0402_1%  [R_0402]  171.2 27.44 270 top
RD30  2_0402_1%  [R_0402]  170.26 26.85 180 top
RD31  24.9_0402_1%  [R_0402]  168.41 28.58 270 top
RE8  100K_0402_5%  [R_0402]  289.06 93.01 90 top
RE10  100K_0402_5%  [R_0402]  275.81 95.66 90 top
RE11  100K_0402_5%  [R_0402]  272.71 75.56 270 top
RE12  100K_0402_5%  [R_0402]  279.67 72.49 270 top
RE20  100K_0402_5%  [R_0402]  273.6 75.56 270 top
RE21  10K_0402_5%  [R_0402]  266.6 90.96 90 top
RE25  100K_0402_5%  [R_0402]  288.11 91.83 270 top
RE26  10_0402_5%  [R_0402]  287.34 91.83 270 top
RE30  0_0201_5%  [R0201_0OHM]  292.39 92.89 0 top
RE31  100K_0402_5%  [R_0402]  266.57 73.73 90 top
RE32  0_0402_5%  [R0402_0OHM]  269.2 73.56 90 top
RE33  1K_0402_5%  [R_0402]  265.8 74.64 270 top
RE35  10K_0402_5%  [R_0402]  283.41 90.11 90 top
RE37  2.2K_0402_5%  [R_0402]  287.03 77.45 0 top
RE38  10K_0402_5%  [R_0402]  281.65 90.2 90 top
RE43  2.2K_0402_5%  [R_0402]  287.03 76.69 0 top
RE48  10K_0402_5%  [R_0402]  195.53 81.33 135 top
RE51  10K_0402_5%  [R_0402]  196.16 81.9 135 top
RE55  100K_0402_5%  [R_0402]  271.05 75.57 270 top
RE56  10K_0402_5%  [R_0402]  278.62 75.56 270 top
RE57  1K_0402_5%  [R_0402]  271.76 73.81 270 top
RE58  100K_0402_5%  [R_0402]  271.81 75.57 270 top
RE59  0_0402_5%  [R0402_0OHM]  281.7 92.98 270 top
RE60  43_0402_5%  [R_0402]  280.12 90.2 90 top
RE63  100K_0402_5%  [R_0402]  274.92 98.2 0 top
RE64  300_0402_5%  [R_0402]  276.7 69.65 270 top
RE65  100_0402_1%  [R_0402]  273.99 98.2 180 top
RE67  10K_0402_5%  [R_0402]  282.03 64.87 90 top
RE68  100K_0402_5%  [R_0402]  280.2 68.81 180 top
RE69  8.2K_0402_5%  [R_0402]  177.68 96.5 90 bottom
RE70  2.2K_0402_5%  [R_0402]  171.95 97.15 0 bottom
RE71  10_0402_1%  [R_0402]  296.5 93.08 180 top
RE72  10K_0402_5%  [R_0402]  293.39 93.66 180 top
RE73  10K_0402_5%  [R_0402]  292.4 96.63 0 top
RE74  10K_0402_5%  [R_0402]  292.4 97.39 0 top
RE75  100K_0402_5%  [R_0402]  293.34 95.19 180 top
RE77  1.58K_0402_1%  [R_0402]  272.99 91.74 90 top
RE79  4.3K_0402_1%  [R_0402]  279.53 97.61 270 top
RE83  100K_0402_5%  [R_0402]  278.09 94.04 270 top
RE84  100K_0402_5%  [R_0402]  277.84 90.2 90 top
RE85  100K_0402_5%  [R_0402]  277.08 90.2 90 top
RE86  10K_0402_5%  [R_0402]  292.41 94.42 0 top
RE90  0_0402_5%  [R0402_0OHM]  172.87 98.67 180 bottom
RE91  100K_0402_5%  [R_0402]  263.84 84.32 0 top
RE92  100K_0402_5%  [R_0402]  272.74 68.62 90 top
RE93  100K_0201_5%  [R_0201]  263.97 89.26 180 top
RE94  75_0402_5%  [R_0402]  263.54 85.27 180 top
RE95  100K_0402_5%  [R_0402]  270.63 71.74 0 top
RE274  0_0201_5%  [R_0201]  283.28 55.59 270 top
RE275  0_0201_5%  [R0201_0OHM]  282.64 55.01 90 top
RE280  0_0201_5%  [R_0201]  177.34 76.83 180 bottom
RE288  100_0402_5%  [R_0402]  280.38 93.08 90 top
RE290  0_0201_5%  [R0201_0OHM]  270.33 78.58 270 top
RE292  0_0201_5%  [R_0201]  174.76 79.7 270 bottom
RE300  33K_0402_5%  [R_0402]  284.61 94.94 270 top
RE301  10K_0402_5%  [R_0402]  271.85 90.47 90 top
RE302  2.2K_0402_5%  [R_0402]  264.03 74.8 0 top
RE303  2.2K_0402_5%  [R_0402]  264.03 73.91 0 top
RE304  0_0201_5%  [R_0201]  180.85 79.72 270 bottom
RE306  0_0201_5%  [R_0201]  292.39 95.88 0 top
RE312  300_0402_5%  [R_0402]  288.6 82.65 0 top
RE313  10K_0402_5%  [R_0402]  288.62 81.85 0 top
RE314  100_0402_1%  [R_0402]  276.03 73.65 0 top
RE318  0_0201_5%  [R0201_0OHM]  277.91 73.74 270 top
RE342  10K_0402_5%  [R_0402]  286.44 79.37 0 top
RE343  130K_0402_5%  [R_0402]  273.69 72.37 90 top
RE349  43K_0402_1%  [R_0402]  288.55 79.89 270 top
RE350  33_0402_5%  [R_0402]  277.97 71.55 90 top
RE361  0_0201_5%  [R0201_0OHM]  285.68 71.81 180 top
RE362  100K_0402_5%  [R_0402]  272.63 72.96 270 top
RE365  100K_0402_5%  [R_0402]  270.26 90.41 90 top
RE505  100K_0402_5%  [R_0402]  280.2 69.7 180 top
RE507  100K_0402_5%  [R_0402]  268.45 80.44 180 top
RE508  100K_0402_5%  [R_0402]  269.25 71.16 90 top
RE524  2.2K_0402_5%  [R_0402]  286.91 83.36 0 top
RE525  2.2K_0402_5%  [R_0402]  286.91 84.12 0 top
RE526  10K_0402_5%  [R_0402]  267.63 90.96 90 top
RE532  4.7K_0402_5%  [R_0402]  289.13 83.42 0 top
RE536  0_0201_5%  [R_0201]  264.32 85.31 0 top
RE539  100_0402_5%  [R_0402]  287.24 95.03 90 top
RE541  100K_0402_5%  [R_0402]  274.09 64.73 270 top
RE543  1M_0402_5%  [R_0402]  276.83 63.89 180 top
RE546  10K_0402_5%  [R_0402]  272.97 67.82 0 top
RE547  100K_0402_5%  [R_0402]  264.23 90.02 90 top
RE548  0_0201_5%  [R0201_0OHM]  279.28 75.51 270 top
RE549  100K_0402_5%  [R_0402]  283.66 74.59 90 top
RE550  100K_0402_5%  [R_0402]  284.11 73.41 270 top
RE551  0_0402_5%  [R_0402]  272.62 67.02 270 top
RE552  0_0201_5%  [R0201_0OHM]  282.54 94.93 270 top
RE561  100K_0402_5%  [R_0402]  287.54 78.21 0 top
RE562  2.2K_0402_5%  [R_0402]  289.79 90.95 90 top
RE565  0_0201_5%  [R0201_0OHM]  273.4 63.81 90 top
RE600  0_0201_5%  [R0201_0OHM]  284.42 97.06 270 top
RE601  0_0201_5%  [R0201_0OHM]  285.2 75.81 270 top
RE602  0_0201_5%  [R0201_0OHM]  285.35 78.1 180 top
RE603  0_0201_5%  [R0201_0OHM]  292.49 87.97 90 top
RE605  100K_0402_5%  [R_0402]  290.58 93.14 90 top
RE606  100K_0402_5%  [R_0402]  277.08 93.76 90 top
RE608  0_0201_5%  [R0201_0OHM]  280.36 72.47 90 top
RE703  0_0201_5%  [R0201_0OHM]  278.47 97.59 270 top
RE704  10K_0402_5%  [R_0402]  289.01 95.79 90 top
RE706  10K_0402_5%  [R_0402]  291.8 91.93 0 top
RE707  10K_0402_5%  [R_0402]  291.8 91.17 0 top
RE708  10K_0402_5%  [R_0402]  290.16 95.79 90 top
RE709  100K_0402_5%  [R_0402]  289.76 84.18 0 top
RE802  1M_0402_5%  [R_0402]  272.73 71.11 0 top
RE803  100K_0402_5%  [R_0402]  290.66 90.95 90 top
RE804  100K_0402_5%  [R_0402]  289.01 90.95 90 top
RE805  100K_0402_5%  [R_0402]  275.93 68.74 90 top
RE806  100K_0402_5%  [R_0402]  278.47 69.65 270 top
RE807  100K_0402_5%  [R_0402]  287.06 75.83 0 top
RE808  100K_0402_5%  [R_0402]  287.08 74.61 0 top
RE809  100K_0402_5%  [R_0402]  281.44 73.16 270 top
RE810  100K_0402_5%  [R_0402]  288.13 95.94 270 top
RE811  100K_0402_5%  [R_0402]  287.34 94.11 270 top
RE812  100K_0402_5%  [R_0402]  265.12 90.94 270 top
RE813  10K_0402_5%  [R_0402]  296.5 92.2 180 top
RE814  10K_0402_5%  [R_0402]  296.5 90.54 180 top
RE815  10K_0402_5%  [R_0402]  296.5 89.72 180 top
RE816  10K_0402_5%  [R_0402]  296.5 91.37 180 top
RE817  0_0201_5%  [R_0201]  285.01 84.56 0 top
RE818  0_0201_5%  [R_0201]  285.01 85.2 0 top
RE819  0_0201_5%  [R_0201]  274.77 90.71 270 top
RE820  100K_0402_5%  [R_0402]  272.73 70.35 0 top
RE821  100K_0402_5%  [R_0402]  285.44 94.02 90 top
RE822  100K_0402_5%  [R_0402]  265.23 80.78 0 top
RE823  100K_0402_5%  [R_0402]  282.4 72.92 270 top
RI13  10K_0402_5%  [R_0402]  290.87 73.77 180 top
RI14  22.1K_0402_1%  [R_0402]  294.04 79.48 180 top
RN37  10K_0402_5%  [R_0402]  19.77 25.84 270 bottom
RN99  0_0201_5%  [R0201_0OHM]  18.89 24.92 90 bottom
RN100  0_0201_5%  [R_0201]  12.03 23.11 90 top
RN129  0_0201_5%  [R0201_0OHM]  32.7 27.12 0 top
RN130  0.01_0805_1%  [R_0805-NPM]  21.68 27.64 90 top
RN131  0.01_0805_1%  [R_0805]  25.18 29.32 90 top
RR3  10K_0402_5%  [R_0402]  291.87 71.3 270 top
RR4  6.2K_0402_1%  [R_0402]  288.94 62.22 180 top
RR5  0_0201_5%  [R0201_0OHM]  295.95 63.31 0 top
RR6  0_0201_5%  [R0201_0OHM]  296.39 65.08 0 top
RR7  0_0201_5%  [R0201_0OHM]  296.39 65.97 0 top
RR8  0_0201_5%  [R0201_0OHM]  296.39 66.73 0 top
RR9  0_0201_5%  [R0201_0OHM]  295.28 62.33 270 top
RR10  0_0201_5%  [R0201_0OHM]  295.92 62.33 270 top
RR19  10K_0402_5%  [R_0402]  288.99 69.09 90 top
RR274  0_0603_5%  [R0603_0OHM]  296.06 71.38 45 top
RT1  3.3K_0201_5%  [R_0201]  39.22 74.1 180 top
RT2  2.2K_0201_5%  [R_0201]  37.05 84.07 0 top
RT3  2.2K_0201_5%  [R_0201]  37.05 83.43 0 top
RT4  3.3K_0201_5%  [R_0201]  37.64 84.64 180 top
RT5  10K_0201_5%  [R_0201]  31.72 81.59 180 top
RT6  10K_0201_5%  [R_0201]  29.09 82.39 270 top
RT7  10K_0201_5%  [R_0201]  31.72 82.16 180 top
RT8  10K_0201_5%  [R_0201]  31.72 80.77 180 top
RT9  0_0201_5%  [R0201_0OHM]  29.56 92.32 0 top
RT12  2.2K_0201_5%  [R_0201]  31.38 84.92 90 top
RT13  2.2K_0201_5%  [R_0201]  32.2 84.92 90 top
RT16  10K_0201_5%  [R_0201]  25.13 86.35 90 top
RT17  10K_0201_5%  [R_0201]  23.37 86.89 90 bottom
RT18  2.2K_0201_5%  [R_0201]  27.98 86.67 180 bottom
RT19  2.2K_0201_5%  [R_0201]  29.05 86.67 0 bottom
RT20  10K_0201_5%  [R_0201]  24.07 86.89 90 bottom
RT21  1M_0201_5%  [R_0201]  21.15 81.02 0 top
RT22  1M_0201_5%  [R_0201]  21.15 80.38 0 top
RT23  100K_0201_5%  [R_0201]  26.42 81.74 90 top
RT24  100K_0201_5%  [R_0201]  33.92 83.34 270 bottom
RT25  100K_0402_5%  [R_0402]  23.35 86.35 90 top
RT26  100K_0201_5%  [R_0201]  22.55 80.99 270 top
RT27  10K_0201_5%  [R_0201]  22.46 86.35 90 top
RT28  100K_0201_5%  [R_0201]  30.23 84.92 90 top
RT29  100K_0201_5%  [R_0201]  31.76 79.79 270 top
RT31  100K_0201_5%  [R_0201]  18.9 80.51 180 bottom
RT32  100K_0201_5%  [R_0201]  18.9 79.88 180 bottom
RT33  100K_0201_5%  [R_0201]  24.96 86.91 90 bottom
RT34  3.01K_0201_1%  [R_0201]  28.29 74.61 0 top
RT35  14K_0201_1%  [R_0201]  32.39 79.2 90 top
RT36  100_0201_5%  [R_0201]  22.55 86.86 90 bottom
RT37  100_0201_5%  [R_0201]  33.92 81.55 90 bottom
RT38  14K_0201_1%  [R_0201]  31.1 74.75 270 top
RT39  4.75K_0402_0.5%  [R_0402]  24.89 79.11 0 top
RT40  0_0201_5%  [R_0201]  19.02 68.43 0 bottom
RT41  499_0201_1%  [R_0201]  24.71 73.18 270 top
RT42  499_0201_1%  [R_0201]  22.19 75.55 270 top
RT48  0_0201_5%  [R0201_0OHM]  26.22 90.93 0 top
RT49  0_0201_5%  [R_0201]  24.09 90.86 180 top
RT50  3.3K_0201_5%  [R_0201]  31.5 46.06 90 top
RT51  3.3K_0201_5%  [R_0201]  33.41 47.52 90 top
RT52  3.3K_0201_5%  [R_0201]  37.38 45.33 180 top
RT53  3.3K_0201_5%  [R_0201]  36.8 44.25 0 top
RT58  0_0201_5%  [R0201_0OHM]  38.02 58.41 180 top
RT59  0_0201_5%  [R0201_0OHM]  38.02 57.4 180 top
RT60  0_0201_5%  [R0201_0OHM]  36.75 59.49 180 top
RT63  0_0201_5%  [R0201_0OHM]  32.16 53.36 270 bottom
RT64  0_0201_5%  [R_0201]  34.02 59.75 180 top
RT65  0_0201_5%  [R_0201]  34.02 60.38 180 top
RT66  3.3K_0201_5%  [R_0201]  36.75 57.4 180 top
RT67  3.3K_0201_5%  [R_0201]  36.75 58.41 180 top
RT68  10K_0201_5%  [R_0201]  36.75 60.06 180 top
RT71  1M_0201_5%  [R_0201]  32.66 61.53 180 top
RT76  10K_0201_1%  [R_0201]  28.74 56.14 180 top
RT81  100K_0201_5%  [R_0201]  31.81 52.72 270 top
RT82  1M_0201_5%  [R_0201]  30.92 52.72 270 top
RT83  0_0201_5%  [R0201_0OHM]  30.91 53.47 0 top
RT86  100K_0201_5%  [R_0201]  32.25 63.08 90 bottom
RT89  0_0201_5%  [R_0201]  25.85 55.28 270 bottom
RT90  0_0201_5%  [R_0201]  25.85 56.03 90 bottom
RT95  100K_0201_5%  [R_0201]  27.89 52.23 180 bottom
RT96  100K_0201_5%  [R_0201]  28.62 52.23 0 bottom
RT97  0_0201_5%  [R_0201]  30.26 62.99 0 bottom
RT98  0_0201_5%  [R_0201]  33.41 49.44 270 top
RT99  0_0201_5%  [R0201_0OHM]  30.26 62.35 0 bottom
RT100  15K_0201_1%  [R_0201]  29.71 53.49 270 top
RT101  100K_0201_5%  [R_0201]  33.66 58.58 270 top
RT103  0_0201_5%  [R_0201]  27.96 63.05 270 bottom
RT104  0_0201_5%  [R0201_0OHM]  27.22 60.76 180 bottom
RT105  0_0201_5%  [R0201_0OHM]  27.16 61.68 180 bottom
RT106  10K_0201_5%  [R_0201]  32.77 53.23 270 top
RT107  10K_0201_5%  [R_0201]  33.92 55.15 270 top
RT110  0_0201_5%  [R_0201]  31.49 63.08 90 bottom
RT111  100K_0402_5%  [R_0402]  23.69 89.67 180 bottom
RT120  0_0201_5%  [R0201_0OHM]  26.44 61.43 90 top
RT121  0_0201_5%  [R0201_0OHM]  25.79 61.42 90 top
RT122  0_0201_5%  [R0201_0OHM]  27.25 62.01 270 top
RT123  0_0201_5%  [R0201_0OHM]  27.88 62.01 270 top
RT128  100K_0201_5%  [R_0201]  31.74 76.65 270 top
RT129  100K_0201_5%  [R_0201]  27.06 81.74 90 top
RT190  2.2_0201_1%  [R_0201]  19.6 72.13 180 bottom
RT191  2.2_0201_1%  [R_0201]  19.6 72.7 180 bottom
RT192  2.2_0201_1%  [R_0201]  19.62 74 180 bottom
RT193  2.2_0201_1%  [R_0201]  19.62 74.63 180 bottom
RT194  2.2_0201_1%  [R_0201]  19.6 78.54 180 bottom
RT195  2.2_0201_1%  [R_0201]  19.6 77.97 180 bottom
RT196  2.2_0201_1%  [R_0201]  19.62 76.56 180 bottom
RT197  2.2_0201_1%  [R_0201]  19.62 75.93 180 bottom
RT219  221K_0201_1%  [R_0201]  11.98 81.85 270 top
RT220  221K_0201_1%  [R_0201]  11.98 82.47 90 top
RT221  221K_0201_1%  [R_0201]  11.22 89.67 90 bottom
RT222  221K_0201_1%  [R_0201]  11.22 89.05 270 bottom
RT338  10K_0201_5%  [R_0201]  34.42 84.92 90 top
RT371  10K_0201_5%  [R_0201]  31.67 86.67 180 bottom
RT372  10K_0201_5%  [R_0201]  24.24 86.35 90 top
RT377  43K_0402_1%  [R_0402]  29.05 58.12 270 top
RT391  10K_0402_5%  [R_0402]  32.96 91.8 90 top
RT393  100K_0402_5%  [R_0402]  25.77 88.7 0 bottom
RT394  0_0201_5%  [R_0201]  21 68.43 180 bottom
RT398  0_0402_5%  [R_0402]  25.53 93.39 90 top
RT399  0_0402_5%  [R0402_0OHM]  27.26 94.29 180 top
RT400  0_0201_5%  [R0201_0OHM]  24.98 57.29 0 top
RT401  0_0201_5%  [R0201_0OHM]  24.98 58.05 0 top
RT402  0_0201_5%  [R_0201]  25.26 57.29 0 bottom
RT403  0_0201_5%  [R_0201]  25.26 58.05 0 bottom
RT440  1M_0201_5%  [R_0201]  38.42 67.98 270 bottom
RT441  0_0201_5%  [R0201_0OHM]  38.42 66.71 270 bottom
RT445  0_0201_5%  [R_0201]  40.65 63.2 90 bottom
RT447  10K_0201_5%  [R_0201]  41.03 68.74 270 bottom
RT448  0_0201_5%  [R0201_0OHM]  39.25 63.2 90 bottom
RT455  10K_0402_5%  [R_0402]  28.47 88.58 180 top
RT456  0_0201_5%  [R0201_0OHM]  41.22 63.2 90 bottom
RT482  0_0201_5%  [R_0201]  34.8 51.64 90 bottom
RT483  0_0201_5%  [R0201_0OHM]  34.17 51.64 90 bottom
RT488  221K_0201_1%  [R_0201]  11.98 81.85 270 bottom
RT489  221K_0201_1%  [R_0201]  11.98 82.47 90 bottom
RT490  221K_0201_1%  [R_0201]  11.22 89.05 270 top
RT491  221K_0201_1%  [R_0201]  11.22 89.67 90 top
RT492  0_0201_5%  [R0201_0OHM]  21.68 46.09 0 top
RT493  0_0201_5%  [R0201_0OHM]  22.23 44.41 90 top
RT494  100K_0201_5%  [R_0201]  25.19 46.73 180 top
RT495  0_0201_5%  [R0201_0OHM]  23.86 46.73 180 top
RT496  0_0201_5%  [R_0201]  21.68 46.73 0 top
RT497  10K_0201_5%  [R_0201]  23.37 73.18 270 top
RV1  4.7K_0402_5%  [R_0402]  67.25 105.99 90 top
RV2  4.7K_0402_5%  [R_0402]  48.44 107.69 0 top
RV3  100K_0402_5%  [R_0402]  101.86 95.51 270 bottom
RV4  270K_0402_5%  [R_0402]  95.74 99.89 270 bottom
RV5  47K_0402_5%  [R_0402]  95.74 100.88 90 bottom
RV6  47K_0402_5%  [R_0402]  83.02 108.49 90 top
RV7  100K_0402_5%  [R_0402]  67.49 109.47 0 top
RV8  10K_0402_5%  [R_0402]  76.62 112.67 0 top
RV10  470_0402_1%  [R_0402]  16.56 53.05 180 top
RV11  470_0402_1%  [R_0402]  16.56 53.92 180 top
RV12  470_0402_1%  [R_0402]  16.55 56.81 180 top
RV13  470_0402_1%  [R_0402]  16.55 57.68 180 top
RV14  470_0402_1%  [R_0402]  16.56 55.02 180 top
RV15  470_0402_1%  [R_0402]  16.56 55.89 180 top
RV16  470_0402_1%  [R_0402]  16.59 58.72 180 top
RV17  470_0402_1%  [R_0402]  16.59 59.6 180 top
RV18  10K_0402_5%  [R_0402]  18.87 61.73 270 top
RV19  10K_0402_5%  [R_0402]  14.87 58.68 270 top
RV20  1M_0402_5%  [R_0402]  16.45 64.76 180 top
RV21  20K_0402_5%  [R_0402]  17.01 68.38 0 top
RV22  2.2K_0402_5%  [R_0402]  8.02 53.46 180 bottom
RV23  2.2K_0402_5%  [R_0402]  8.02 54.41 180 bottom
RV26  130_0402_5%  [R_0402]  15.43 54 270 bottom
RV29  130_0402_5%  [R_0402]  15.41 57.73 270 bottom
RV32  130_0402_5%  [R_0402]  15.41 55.93 270 bottom
RV35  130_0402_5%  [R_0402]  15.42 59.54 270 bottom
RV56  5.6_0402_5%  [R_0402]  17.42 53.12 180 bottom
RV57  5.6_0402_5%  [R_0402]  17.42 53.99 180 bottom
RV58  5.6_0402_5%  [R_0402]  17.39 56.84 180 bottom
RV59  5.6_0402_5%  [R_0402]  17.39 57.72 180 bottom
RV60  5.6_0402_5%  [R_0402]  17.39 55.05 180 bottom
RV61  5.6_0402_5%  [R_0402]  17.4 55.93 180 bottom
RV62  5.6_0402_5%  [R_0402]  17.44 58.78 180 bottom
RV63  5.6_0402_5%  [R_0402]  17.44 59.65 180 bottom
RV98  2.2K_0201_5%  [R_0201]  88.33 107.86 270 top
RV99  2.2K_0201_5%  [R_0201]  90.28 105.78 180 top
RV101  0.01_1206_1%  [R_1206]  106.94 101.66 270 bottom
RV102  20K_0201_5%  [R_0201]  100.67 98.09 135 bottom
RV311  100K_0201_5%  [R_0201]  89.76 108.32 0 top
RV319  1K_0201_5%  [R_0201]  89.76 108.96 0 top
RV323  0_0201_5%  [R0201_0OHM]  84.37 107.31 180 top
RV324  0_0201_5%  [R_0201]  84.37 106.66 180 top
RV325  10K_0402_5%  [R_0402]  94.94 110.05 270 top
RV326  100K_0402_5%  [R_0402]  83.78 109.4 270 top
RV400  0_0201_5%  [R0201_0OHM]  79.14 106.77 180 top
RV623  100K_0402_5%  [R_0402]  86.12 102.34 0 top
RV624  1M_0402_5%  [R_0402]  87.83 102.34 0 top
RV625  47K_0402_5%  [R_0402]  77.4 103.87 90 top
RV626  200K_0402_5%  [R_0402]  70.83 103.49 270 top
RV627  10K_0402_5%  [R_0402]  72.61 102.77 90 top
RV628  0_0201_5%  [R0201_0OHM]  89.45 101.94 0 top
RV629  200K_0402_5%  [R_0402]  90.13 105.04 270 top
RV630  47K_0402_5%  [R_0402]  92.53 101.21 270 top
RV631  10K_0402_5%  [R_0402]  91 104.12 90 top
RV732  0_0603_5%  [R_0603]  80.67 110.47 0 top
RV733  0_0603_5%  [R0603_0OHM]  80.67 109.2 0 top
RV734  10K_0402_5%  [R_0402]  95.19 108.4 270 top
RV740  2.2K_0201_5%  [R_0201]  99.68 107.25 180 top
RV741  2.2K_0201_5%  [R_0201]  99.68 107.88 180 top
RV742  2.2K_0201_5%  [R_0201]  99.96 108.79 90 top
RV743  10K_0201_5%  [R_0201]  100.65 108.79 90 top
RV744  10K_0201_5%  [R_0201]  101.29 108.79 90 top
RZ8  2.2K_0402_5%  [R_0402]  271.94 30.25 180 top
RZ9  2.2K_0402_5%  [R_0402]  271.94 29.49 180 top
RZ10  100K_0402_5%  [R_0402]  270.97 32.3 90 top
RZ18  4.7K_0402_5%  [R_0402]  250.04 30.58 270 top
RZ19  4.7K_0402_5%  [R_0402]  252.34 32.38 0 top
RZ20  2.2K_0402_5%  [R_0402]  251.61 34.95 270 bottom
RZ21  2.2K_0402_5%  [R_0402]  251.61 35.69 90 bottom
RZ22  0_0201_5%  [R_0201]  249.21 30.56 270 top
RZ23  0_0201_5%  [R_0201]  253.9 30.73 270 top
RZ25  150_0402_5%  [R_0402]  307.84 9.77 270 bottom
RZ26  0_0201_5%  [R0201_0OHM]  252.36 33.98 0 bottom
RZ28  150_0402_5%  [R_0402]  307.84 11.41 270 bottom
RZ29  0_0201_5%  [R0201_0OHM]  252.36 36.52 0 bottom
RZ32  1K_0402_5%  [R_0402]  308.58 72.62 180 bottom
RZ38  100K_0402_5%  [R_0402]  266.03 46.54 270 top
RZ40  100K_0402_5%  [R_0402]  259.77 50.89 90 top
RZ43  100K_0402_5%  [R_0402]  270 61.84 0 top
